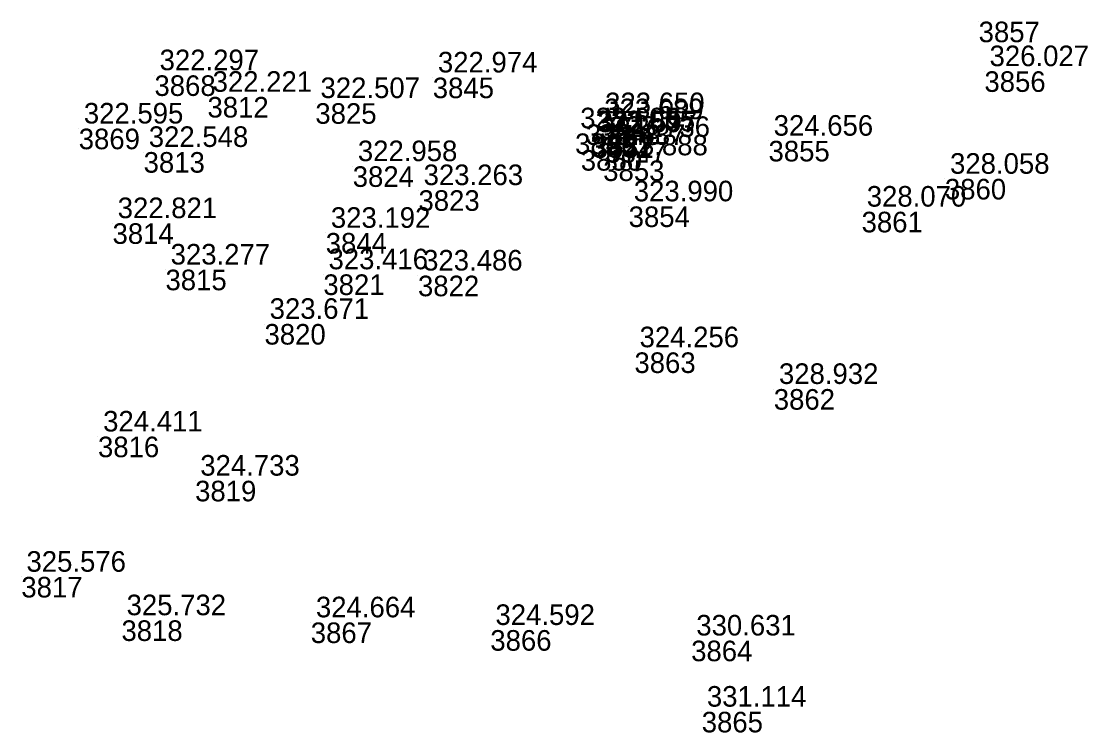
# Model space of a CAD drawing. Extents: x -829398 to -819400, y -1074439 to -1067977.
# Drawn here: x -827198.9 to -827136.7, y -1070271.1 to -1070229.6 of the extents above; entities that cross this region are included whole.
import ezdxf

# ---------------------------------------------------------------- set-up
doc = ezdxf.new("R2010")
doc.units = 0
doc.layers.add('Vrstva 60', color=7, linetype='Continuous')
doc.layers.add('Vrstva 61', color=7, linetype='Continuous')

msp = doc.modelspace()

# ---------------------------------------------------------------- linework, layer by layer
at = {"layer": 'Vrstva 60'}
for p, q in [((-827143.067, -1070229.607), (-827143.067, -1070229.607)), ((-827191.121, -1070232.74), (-827191.121, -1070232.74)), ((-827174.893, -1070232.87), (-827174.893, -1070232.87)), ((-827142.729, -1070232.504), (-827142.729, -1070232.504)), ((-827188.03, -1070233.999), (-827188.03, -1070233.999)), ((-827181.74, -1070234.364), (-827181.74, -1070234.364)), ((-827165.144, -1070235.245), (-827165.144, -1070235.245)), ((-827195.537, -1070235.848), (-827195.537, -1070235.848)), ((-827166.596, -1070236.128), (-827166.596, -1070236.128)), ((-827165.197, -1070235.597), (-827165.197, -1070235.597)), ((-827165.7, -1070236.303), (-827165.7, -1070236.303)), ((-827165.578, -1070236.357), (-827165.578, -1070236.357)), ((-827164.831, -1070236.632), (-827164.831, -1070236.632)), ((-827155.318, -1070236.559), (-827155.318, -1070236.559)), ((-827191.752, -1070237.215), (-827191.752, -1070237.215)), ((-827166.263, -1070237.095), (-827166.263, -1070237.095)), ((-827179.561, -1070238.044), (-827179.561, -1070238.044)), ((-827164.956, -1070237.701), (-827164.956, -1070237.701)), ((-827145.033, -1070238.778), (-827145.033, -1070238.778)), ((-827175.727, -1070239.44), (-827175.727, -1070239.44)), ((-827163.473, -1070240.385), (-827163.473, -1070240.385)), ((-827149.89, -1070240.695), (-827149.89, -1070240.695)), ((-827193.565, -1070241.367), (-827193.565, -1070241.367)), ((-827181.135, -1070241.931), (-827181.135, -1070241.931)), ((-827190.478, -1070244.071), (-827190.478, -1070244.071)), ((-827181.273, -1070244.348), (-827181.273, -1070244.348)), ((-827175.756, -1070244.421), (-827175.756, -1070244.421)), ((-827184.705, -1070247.24), (-827184.705, -1070247.24)), ((-827163.136, -1070248.896), (-827163.136, -1070248.896)), ((-827155.01, -1070251.036), (-827155.01, -1070251.036)), ((-827194.413, -1070253.808), (-827194.413, -1070253.808)), ((-827188.75, -1070256.382), (-827188.75, -1070256.382)), ((-827198.883, -1070261.987), (-827198.883, -1070261.987)), ((-827193.046, -1070264.523), (-827193.046, -1070264.523)), ((-827182.007, -1070264.645), (-827182.007, -1070264.645)), ((-827171.539, -1070265.091), (-827171.539, -1070265.091)), ((-827159.828, -1070265.705), (-827159.828, -1070265.705)), ((-827159.21, -1070269.855), (-827159.21, -1070269.855))]:
    msp.add_line(p, q, dxfattribs=at)

# ---------------------------------------------------------------- texts
for s, p in [('3857', (-827143.067, -1070230.807)), ('3868', (-827191.121, -1070233.94)), ('3845', (-827174.893, -1070234.07)), ('3856', (-827142.729, -1070233.704)), ('3812', (-827188.03, -1070235.199)), ('3825', (-827181.74, -1070235.564)), ('3846', (-827165.144, -1070236.445)), ('3869', (-827195.537, -1070237.048)), ('3849', (-827166.596, -1070237.328)), ('3848', (-827165.197, -1070236.797)), ('3851', (-827165.7, -1070237.503)), ('3852', (-827165.578, -1070237.557)), ('3847', (-827164.831, -1070237.832)), ('3855', (-827155.318, -1070237.759)), ('3813', (-827191.752, -1070238.415)), ('3850', (-827166.263, -1070238.295)), ('3824', (-827179.561, -1070239.244)), ('3853', (-827164.956, -1070238.901)), ('3860', (-827145.033, -1070239.978)), ('3823', (-827175.727, -1070240.64)), ('3854', (-827163.473, -1070241.585)), ('3861', (-827149.89, -1070241.895)), ('3814', (-827193.565, -1070242.567)), ('3844', (-827181.135, -1070243.131)), ('3815', (-827190.478, -1070245.271)), ('3821', (-827181.273, -1070245.548)), ('3822', (-827175.756, -1070245.621)), ('3820', (-827184.705, -1070248.44)), ('3863', (-827163.136, -1070250.096)), ('3862', (-827155.01, -1070252.236)), ('3816', (-827194.413, -1070255.008)), ('3819', (-827188.75, -1070257.582)), ('3817', (-827198.883, -1070263.187)), ('3818', (-827193.046, -1070265.723)), ('3867', (-827182.007, -1070265.845)), ('3866', (-827171.539, -1070266.291)), ('3864', (-827159.828, -1070266.905)), ('3865', (-827159.21, -1070271.055))]:
    msp.add_text(s, height=1.2, dxfattribs=at).set_placement(p)
at = {"layer": 'Vrstva 61'}
for s, p in [('326.027', (-827142.429, -1070232.204)), ('322.297', (-827190.821, -1070232.44)), ('322.974', (-827174.593, -1070232.57)), ('322.221', (-827187.73, -1070233.699)), ('322.507', (-827181.44, -1070234.064)), ('323.689', (-827164.897, -1070235.297)), ('323.650', (-827164.844, -1070234.945)), ('322.595', (-827195.237, -1070235.548)), ('323.605', (-827166.296, -1070235.828)), ('323.665', (-827165.4, -1070236.003)), ('322.597', (-827165.278, -1070236.057)), ('323.736', (-827164.531, -1070236.332)), ('324.656', (-827155.018, -1070236.259)), ('322.548', (-827191.452, -1070236.915)), ('323.637', (-827165.963, -1070236.795)), ('323.888', (-827164.656, -1070237.401)), ('322.958', (-827179.261, -1070237.744)), ('328.058', (-827144.733, -1070238.478)), ('323.263', (-827175.427, -1070239.14)), ('323.990', (-827163.173, -1070240.085)), ('328.070', (-827149.59, -1070240.395)), ('322.821', (-827193.265, -1070241.067)), ('323.192', (-827180.835, -1070241.631)), ('323.277', (-827190.178, -1070243.771)), ('323.416', (-827180.973, -1070244.048)), ('323.486', (-827175.456, -1070244.121)), ('323.671', (-827184.405, -1070246.94)), ('324.256', (-827162.836, -1070248.596)), ('328.932', (-827154.71, -1070250.736)), ('324.411', (-827194.113, -1070253.508)), ('324.733', (-827188.45, -1070256.082)), ('325.576', (-827198.583, -1070261.687)), ('325.732', (-827192.746, -1070264.223)), ('324.664', (-827181.707, -1070264.345)), ('324.592', (-827171.239, -1070264.791)), ('330.631', (-827159.528, -1070265.405)), ('331.114', (-827158.91, -1070269.555))]:
    msp.add_text(s, height=1.2, dxfattribs=at).set_placement(p)

doc.saveas('drawing.dxf')
